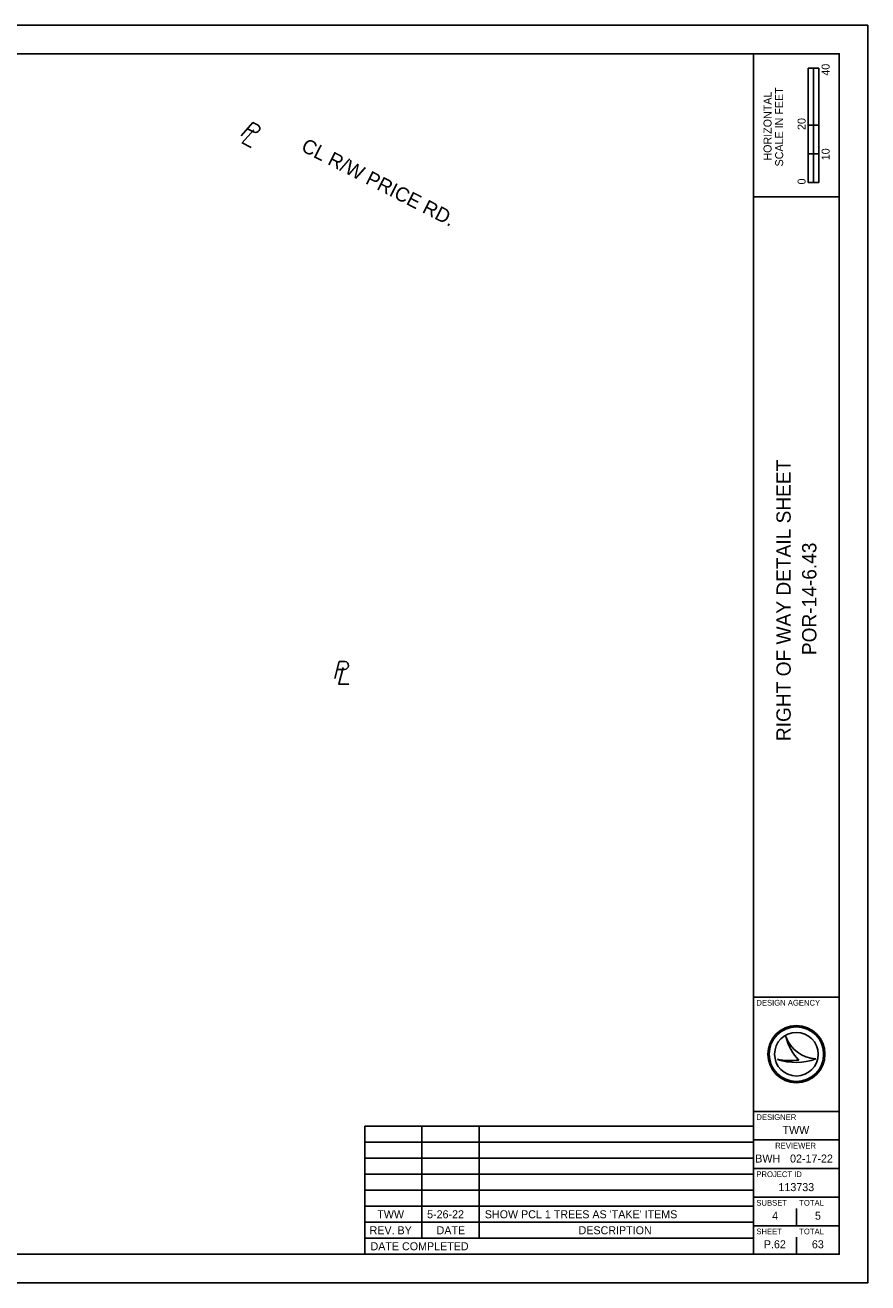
# Model space of a CAD drawing. Extents: x 32.1 to 68.1, y -26.6 to -4.4.
# Drawn here: x 53.37 to 68.12, y -26.35 to -4.35 of the extents above; entities that cross this region are included whole.
import ezdxf

# ---------------------------------------------------------------- set-up
doc = ezdxf.new("R2010")
doc.units = 0
for name, color, linetype in [('_CIVIL_CONSTRUCTION', 7, 'Continuous'), ('DT_X_Contour_Minor', 7, 'Continuous'), ('PV_X_EOP', 7, 'Continuous'), ('PV_X_Shoulder', 7, 'Continuous'), ('SC_Scratch1', 7, 'Continuous')]:
    doc.layers.add(name, color=color, linetype=linetype)

msp = doc.modelspace()

# ---------------------------------------------------------------- linework, layer by layer
at = {"layer": '_CIVIL_CONSTRUCTION'}
for p, q in [((59.313, -23.613), (59.313, -25.853)), ((59.313, -23.613), (66.116, -23.613)), ((60.313, -23.613), (60.313, -25.573)), ((61.313, -23.613), (61.313, -25.573)), ((59.313, -23.893), (66.116, -23.893)), ((59.313, -24.173), (66.116, -24.173)), ((59.313, -24.453), (66.116, -24.453)), ((59.313, -24.733), (66.116, -24.733)), ((59.313, -25.013), (66.116, -25.013)), ((59.313, -25.293), (66.116, -25.293)), ((59.313, -25.573), (66.116, -25.573)), ((66.116, -25.853), (66.116, -25.853))]:
    msp.add_line(p, q, dxfattribs=at)
at = {"layer": 'DT_X_Contour_Minor'}
for p, q in [((57.26, -6.165), (57.376, -6.223)), ((57.304, -6.257), (57.304, -6.257)), ((58.829, -15.621), (58.958, -15.621)), ((58.909, -15.684), (58.909, -15.684))]:
    msp.add_line(p, q, dxfattribs=at)
for points in [[(57.151, -6.289), (57.354, -6.058), (57.446, -6.105)], [(57.371, -6.183), (57.168, -6.412), (57.324, -6.49)], [(58.787, -15.78), (58.865, -15.484), (58.968, -15.484)], [(58.936, -15.588), (58.856, -15.883), (59.031, -15.883)]]:
    msp.add_lwpolyline(points, dxfattribs=at)
for centre, start, end in [((57.406, -6.161), 243.9034, 54.7605), ((58.958, -15.552), 270.471, 81.3281)]:
    msp.add_arc(centre, 0.069, start, end, dxfattribs=at)
at = {"layer": 'PV_X_EOP'}
msp.add_lwpolyline([(34.116, -26.353), (68.116, -26.353), (68.116, -4.353), (34.116, -4.353)], close=True, dxfattribs=at)
at = {"layer": 'PV_X_Shoulder'}
for p, q in [((67.073, -7.103), (67.073, -5.103)), ((67.261, -5.103), (67.073, -5.103)), ((67.073, -6.103), (67.073, -5.103)), ((67.073, -5.103), (67.166, -5.103)), ((67.166, -5.103), (67.167, -5.103)), ((67.167, -5.103), (67.167, -6.103)), ((67.261, -5.103), (67.261, -7.103)), ((67.167, -6.103), (67.073, -6.103)), ((67.26, -6.103), (67.166, -6.103)), ((67.166, -6.103), (67.166, -6.603)), ((67.26, -6.603), (67.26, -6.103)), ((67.166, -6.603), (67.073, -6.603)), ((67.073, -6.603), (67.073, -7.103)), ((67.166, -7.103), (67.166, -6.603)), ((67.166, -6.603), (67.26, -6.603)), ((67.261, -7.103), (67.073, -7.103)), ((67.073, -7.103), (67.166, -7.103)), ((66.684, -22.043), (66.684, -22.043)), ((66.866, -22.353), (66.866, -22.353)), ((67.204, -22.434), (67.204, -22.434)), ((66.534, -22.443), (66.534, -22.443)), ((66.866, -25.353), (66.866, -25.053)), ((66.491, -25.678), (66.491, -25.678)), ((66.866, -25.853), (66.866, -25.553))]:
    msp.add_line(p, q, dxfattribs=at)
for radius in [0.5, 0.477, 0.477, 0.382]:
    msp.add_circle((66.866, -22.353), radius, dxfattribs=at)
for centre, radius, start, end in [((67.232, -21.855), 0.58, 198.9257, 198.9319), ((67.463, -21.883), 0.796, 191.6379, 191.6421), ((67.232, -21.855), 0.58, 198.9319, 267.1657), ((67.463, -21.883), 0.796, 191.6421, 226.0947), ((66.856, -21.483), 1.013, 251.4576, 290.0832), ((66.764, -21.198), 1.266, 259.4964, 259.4995), ((66.856, -21.483), 1.013, 251.4527, 251.4576), ((66.764, -21.198), 1.266, 259.4995, 276.6672)]:
    msp.add_arc(centre, radius, start, end, dxfattribs=at)
at = {"layer": 'SC_Scratch1'}
for p, q in [((66.116, -25.853), (66.116, -4.853)), ((66.116, -7.353), (67.616, -7.353)), ((66.116, -21.353), (67.616, -21.353)), ((66.116, -23.353), (67.616, -23.353)), ((66.116, -23.853), (67.616, -23.853)), ((66.116, -24.353), (67.616, -24.353)), ((66.116, -24.853), (67.616, -24.853)), ((66.116, -25.353), (67.616, -25.353))]:
    msp.add_line(p, q, dxfattribs=at)
msp.add_lwpolyline([(35.616, -4.853), (67.616, -4.853), (67.616, -25.853), (35.616, -25.853)], close=True, dxfattribs=at)

# ---------------------------------------------------------------- texts
at = {"layer": '_CIVIL_CONSTRUCTION'}
msp.add_text('CL R/W PRICE RD.', height=0.25, rotation=333.0494, dxfattribs=at).set_placement((58.181, -6.543))
for s, p in [('TWW', (59.531, -25.223)), (' 5-26-22', (60.351, -25.223)), ("SHOW PCL 1 TREES AS 'TAKE' ITEMS      ", (61.413, -25.223)), ('REV. BY', (59.397, -25.503)), ('DATE', (60.569, -25.503)), ('DESCRIPTION', (63.054, -25.503)), ('DATE COMPLETED', (59.413, -25.783))]:
    msp.add_text(s, height=0.14, dxfattribs=at).set_placement(p)
at = {"layer": 'PV_X_Shoulder'}
for s, height, p in [('40', 0.14, (67.447, -5.236)), ('SCALE IN FEET', 0.14, (66.634, -6.824)), ('HORIZONTAL', 0.14, (66.431, -6.722)), ('20', 0.14, (67.027, -6.186)), ('10', 0.14, (67.447, -6.716)), ('0', 0.14, (67.027, -7.139)), ('RIGHT OF WAY DETAIL SHEET', 0.25, (66.766, -16.876)), ('POR-14-6.43', 0.25, (67.216, -15.373))]:
    msp.add_text(s, height=height, rotation=90, dxfattribs=at).set_placement(p)
for s, height, p in [('DESIGN AGENCY', 0.1, (66.166, -21.503)), ('DESIGNER', 0.1, (66.166, -23.503)), ('TWW', 0.14, (66.623, -23.748)), ('REVIEWER', 0.1, (66.495, -24.003)), ('BWH', 0.14, (66.146, -24.248)), ('02-17-22', 0.14, (66.755, -24.248)), ('PROJECT ID', 0.1, (66.166, -24.503)), ('113733', 0.14, (66.552, -24.748)), ('SUBSET', 0.1, (66.166, -25.003)), ('TOTAL', 0.1, (66.916, -25.003)), ('4', 0.14, (66.442, -25.248)), ('5', 0.14, (67.191, -25.248)), ('SHEET', 0.1, (66.166, -25.503)), ('TOTAL', 0.1, (66.916, -25.503)), ('P.62', 0.14, (66.296, -25.748)), ('63', 0.14, (67.137, -25.748))]:
    msp.add_text(s, height=height, dxfattribs=at).set_placement(p)

doc.saveas('drawing.dxf')
